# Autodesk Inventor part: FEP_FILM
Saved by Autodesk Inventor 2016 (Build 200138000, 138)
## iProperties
Created: 2016-01
Part Number: FEP_FILM
Material: Generic
Document SubType Name: Modeling
Designer: John
Density: 1 g/cm^3
Appearance: Default
Author: John
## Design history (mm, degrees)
feature "Base1"
body "Solid1"
